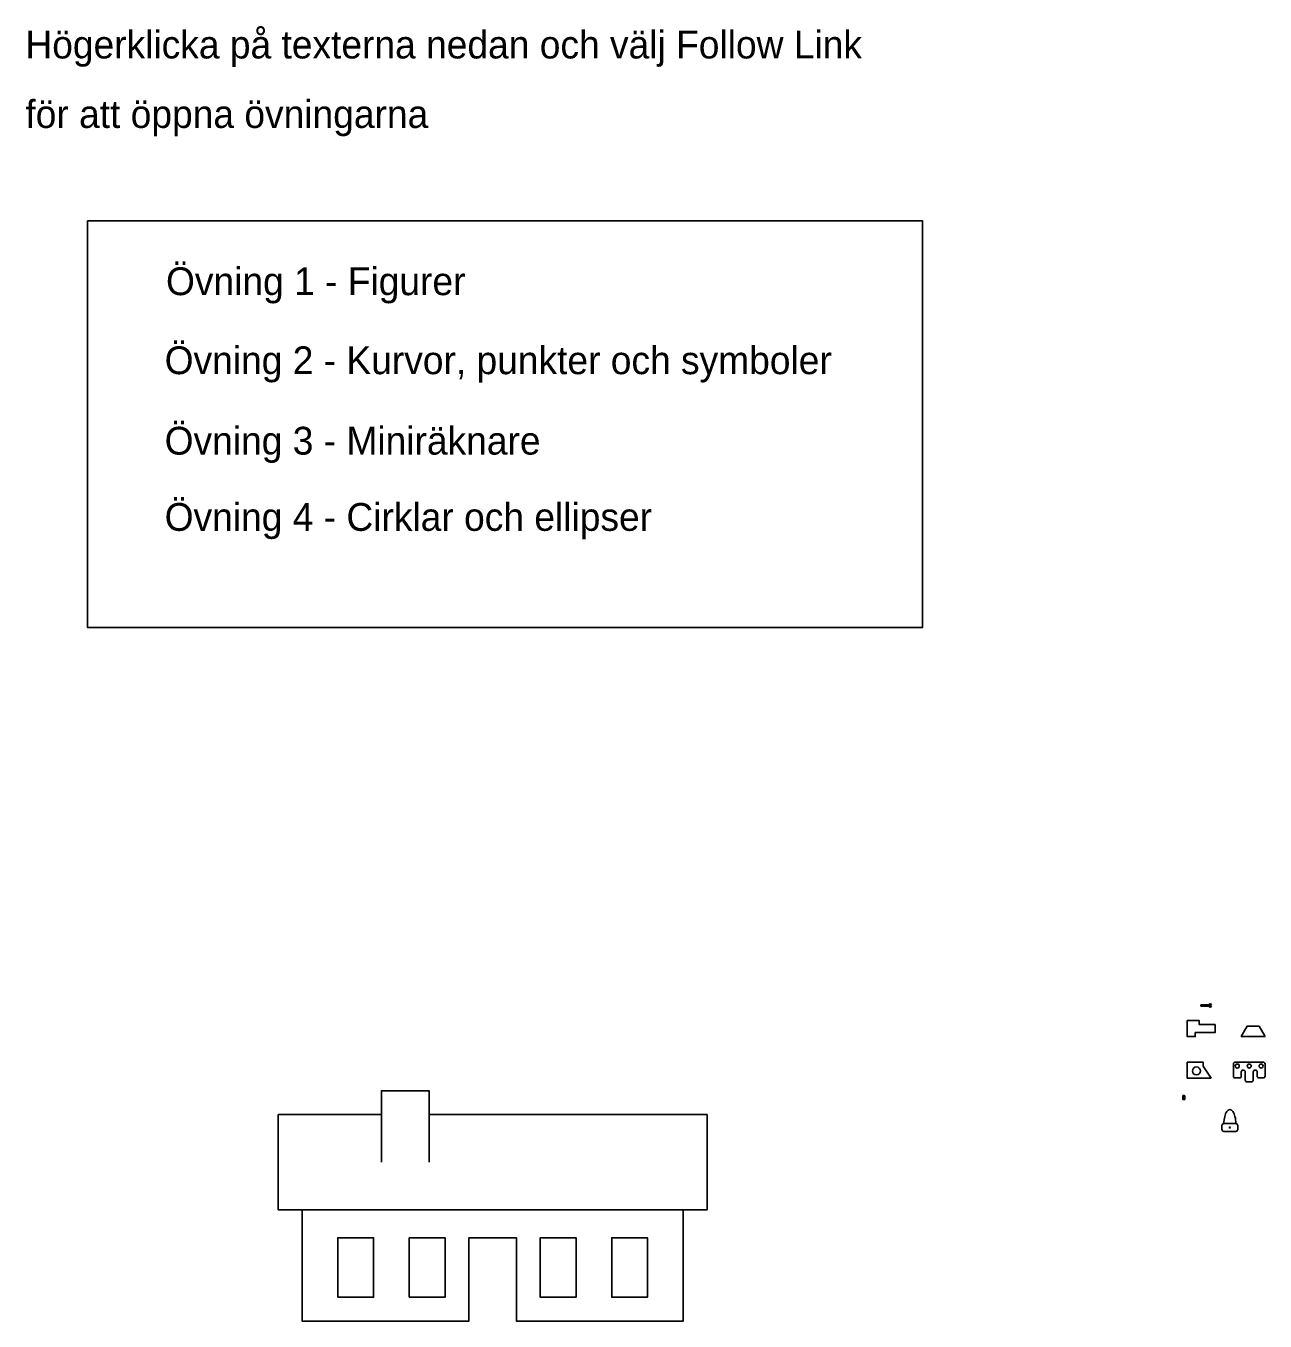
# Model space of a CAD drawing. Extents: x -10680 to 20534, y 503 to 33123.
import ezdxf

# ---------------------------------------------------------------- set-up
doc = ezdxf.new("R2010")
doc.units = 0
doc.layers.add('Default', color=7, linetype='Continuous')
doc.layers.add('Instruktioner', color=7, linetype='Continuous')

msp = doc.modelspace()

# ---------------------------------------------------------------- linework, layer by layer
at = {"layer": 'Default'}
for p, q in [((18922, 8466), (19122, 8466)), ((19122, 8436), (18922, 8436)), ((19734, 6676), (19734, 6976)), ((19784, 7026), (20484, 7026)), ((20534, 6976), (20534, 6676)), ((19884, 6626), (19784, 6626)), ((19934, 6776), (19934, 6676)), ((19984, 6826), (19984, 6826)), ((20034, 6576), (20034, 6776)), ((20184, 6526), (20084, 6526)), ((20234, 6776), (20234, 6576)), ((20284, 6826), (20284, 6826)), ((20334, 6676), (20334, 6776)), ((20484, 6626), (20384, 6626)), ((18461, 6086), (18461, 6176)), ((18466, 6181), (18506, 6181)), ((18506, 6081), (18466, 6081)), ((18511, 6176), (18511, 6086)), ((19446, 5429), (19446, 5329)), ((19796, 5479), (19496, 5479)), ((19496, 5279), (19796, 5279)), ((19846, 5329), (19846, 5429))]:
    msp.add_line(p, q, dxfattribs=at)
for points in [[(19182, 8466), (19152, 8466), (19152, 8436), (19182, 8436)], [(-1723, 4503), (-1723, 6303), (-523, 6303), (-523, 4503)], [(-3723, 3303), (-4323, 3303), (-4323, 5703), (-1723, 5703)], [(-523, 5703), (6477, 5703), (6477, 3303), (5877, 3303)], [(-3723, 3303), (-3723, 503), (477, 503), (477, 2603), (1677, 2603), (1677, 503), (5877, 503), (5877, 3303), (-3723, 3303)], [(-2823, 1103), (-2823, 2603), (-1923, 2603), (-1923, 1103), (-2823, 1103)], [(-1023, 1103), (-1023, 2603), (-123, 2603), (-123, 1103), (-1023, 1103)], [(3177, 2603), (3177, 1103), (2277, 1103), (2277, 2603), (3177, 2603)], [(4977, 2603), (4977, 1103), (4077, 1103), (4077, 2603), (4977, 2603)]]:
    msp.add_lwpolyline(points, dxfattribs=at)
for points in [[(18575, 8070), (18875, 8070), (18875, 7970), (19275, 7970), (19275, 7770), (18775, 7770), (18775, 7670), (18575, 7670)], [(20534, 7673), (19934, 7673), (20084, 7933), (20384, 7933)], [(19175, 6623), (18575, 6623), (18575, 7023), (18975, 7023), (18975, 6923)], [(18466, 6171), (18506, 6171), (18506, 6146), (18466, 6146)], [(18466, 6121), (18476, 6121), (18476, 6126), (18466, 6126)], [(18466, 6111), (18476, 6111), (18476, 6116), (18466, 6116)], [(18466, 6101), (18476, 6101), (18476, 6106), (18466, 6106)], [(18466, 6091), (18476, 6091), (18476, 6096), (18466, 6096)], [(18481, 6121), (18491, 6121), (18491, 6126), (18481, 6126)], [(18481, 6111), (18491, 6111), (18491, 6116), (18481, 6116)], [(18481, 6101), (18491, 6101), (18491, 6106), (18481, 6106)], [(18481, 6091), (18491, 6091), (18491, 6096), (18481, 6096)], [(18496, 6121), (18506, 6121), (18506, 6126), (18496, 6126)], [(18496, 6111), (18506, 6111), (18506, 6116), (18496, 6116)], [(18496, 6101), (18506, 6101), (18506, 6106), (18496, 6106)], [(18496, 6091), (18506, 6091), (18506, 6096), (18496, 6096)], [(-3723, 3303), (5877, 3303), (5877, 503), (1677, 503), (1677, 2603), (477, 2603), (477, 503), (-3723, 503)], [(-2823, 1103), (-1923, 1103), (-1923, 2603), (-2823, 2603)], [(-1023, 1103), (-123, 1103), (-123, 2603), (-1023, 2603)], [(3177, 1103), (2277, 1103), (2277, 2603), (3177, 2603)], [(4977, 1103), (4077, 1103), (4077, 2603), (4977, 2603)]]:
    msp.add_lwpolyline(points, close=True, dxfattribs=at)
for centre, radius in [((18805, 6803), 100), ((19834, 6926), 50), ((20134, 6926), 50), ((20434, 6926), 50), ((18469, 6139), 3), ((18478, 6139), 3), ((18486, 6139), 3), ((18495, 6139), 3), ((18503, 6139), 3), ((19646, 5379), 15)]:
    msp.add_circle(centre, radius, dxfattribs=at)
for centre, radius, start, end in [((19152, 8466), 30, 0, 180), ((18922, 8451), 15, 90, 270), ((19152, 8436), 30, 180, 0), ((19784, 6976), 50, 90, 180), ((20484, 6976), 50, 0, 90), ((19784, 6676), 50, 180, 270), ((19884, 6676), 50, 270, 0), ((19984, 6776), 50, 90, 180), ((19984, 6776), 50, 0, 90), ((20084, 6576), 50, 180, 270), ((20184, 6576), 50, 270, 0), ((20284, 6776), 50, 90, 180), ((20284, 6776), 50, 0, 90), ((20384, 6676), 50, 180, 270), ((20484, 6676), 50, 270, 0), ((18466, 6176), 5, 90, 180), ((18466, 6086), 5, 180, 270), ((18506, 6176), 5, 0, 90), ((18506, 6086), 5, 270, 0), ((19496, 5429), 50, 90, 180), ((19496, 5329), 50, 180, 270), ((19796, 5429), 50, 0, 90), ((19796, 5329), 50, 270, 0)]:
    msp.add_arc(centre, radius, start, end, dxfattribs=at)
msp.add_ellipse((19646, 5479), major_axis=(0, 350), ratio=0.428571, start_param=4.712389, end_param=7.853982, dxfattribs=at)
at = {"layer": 'Instruktioner'}
msp.add_lwpolyline([(-9125, 28215), (11901, 28215), (11901, 17970), (-9125, 17970)], close=True, dxfattribs=at)

# ---------------------------------------------------------------- texts
for s, p in [('Högerklicka på texterna nedan och välj Follow Link', (-10693, 32303)), ('för att öppna övningarna', (-10693, 30553)), ('Övning 1 - Figurer', (-7151, 26342)), ('Övning 2 - Kurvor, punkter och symboler', (-7185, 24352)), ('Övning 3 - Miniräknare', (-7185, 22326)), ('Övning 4 - Cirklar och ellipser', (-7185, 20406))]:
    msp.add_text(s, height=700, dxfattribs=at).set_placement(p)

doc.saveas('drawing.dxf')
